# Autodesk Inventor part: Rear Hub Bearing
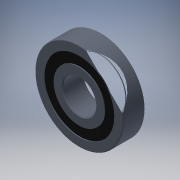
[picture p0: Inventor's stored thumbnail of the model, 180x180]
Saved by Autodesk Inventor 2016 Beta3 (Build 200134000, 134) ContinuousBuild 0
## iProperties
Shininess: 50.0
Compacted: True
Length Units: 11272
Angle Units: 11279
Time Units: 11290
Mass Units: 11286
Length Display Precision: 4
Angle Display Precision: 2
Company: Autodesk
Created: 2000-05
Part Number: Rear Hub Bearing
Project: Inventor Samples
User Status: IN PROGRESS
Document SubType Name: Modeling
Designer: Autodesk, Inc.
Density: 8.08 g/cm^3
Material: Stainless Steel
Mass: 2.70813 g
Surface Area: 3.99293 cm^2
Volume: 0.335165 cm^3
Appearance: Dark Grey
Density: 0.0
Volumn: 0.0
Area: 0.0
PropertySet Name: Model Information
Control State: 0
Master: False
Checked Out: False
Author: Autodesk, Inc.
Revision Number: A
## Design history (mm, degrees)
node "Extrusion1" dims "d5" = 3.175, "d6" = 0
  sketch "Sketch2"
    geometry: C1 r 2.381 at (10.478, 10.795); C2 r 6.35 at (10.478, 10.795); C3 r 5.08 at (10.478, 10.795); C4 r 3.651 at (10.478, 10.795)
    constraints: 4 centre point, 2 coincident, 1 concentric, 1 other
    dimensions: "d1" = 12.7 diameter of C2; "d2" = 1.27 radial gap between concentric circles of C2 C3; "d4" = 1.27 radial gap between concentric circles of C1 C4; "d15" = 4.7625 diameter of C1
workplane "Work Plane1"
node "Fillet1" dims "d12" = 0.127
node "Chamfer1" dims "d13" = 0.127, "d14" = 0.127, "d18" = 45 deg
node "Extrusion2" dims "d16" = 2.921 (computed from d5), "d17" = 0
  sketch "Sketch4"
    geometry: C1 r 5.08 at (0, 0) reference; C2 r 3.651 at (0, 0) reference
body "Solid1"
other parameters: "d7" = -1.5875 (= -0.5 x d5)
